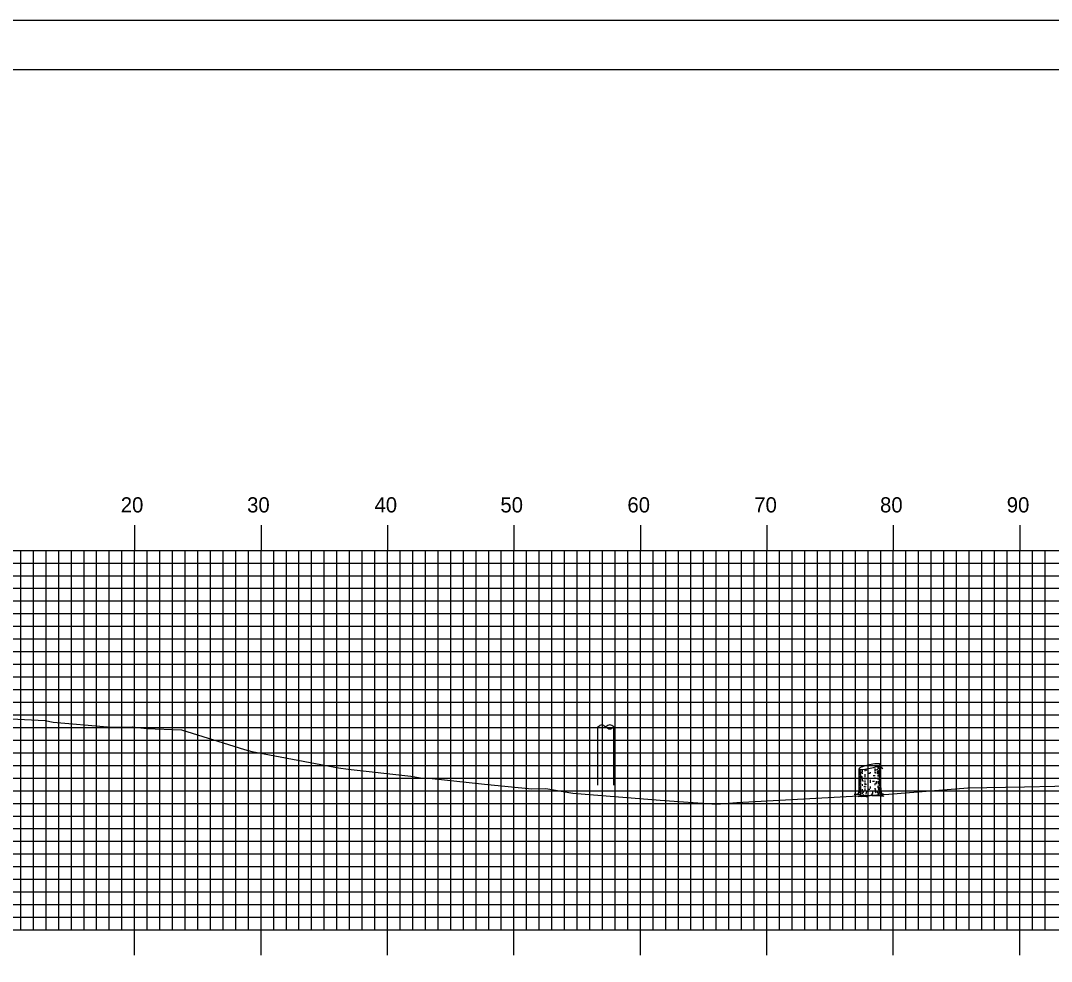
# Model space of a CAD drawing. Extents: x 851300 to 851643, y 366898 to 367118.
# Drawn here: x 851476.5 to 851558, y 367044 to 367118.4 of the extents above; entities that cross this region are included whole.
import ezdxf

# ---------------------------------------------------------------- set-up
doc = ezdxf.new("R2010")
doc.units = 0
for name, color, linetype in [('BORDER', 7, 'Continuous'), ('H_V ANNOTATION', 7, 'Continuous'), ('M_Trees_Conifer_Pay', 7, 'Continuous'), ('MAJOR', 7, 'Continuous'), ('MINOR', 7, 'Continuous'), ('PLOT BOUNDARY', 7, 'Continuous'), ('S_Roadway_Centerline', 7, 'Continuous'), ('S_Utilities_Pole_Power', 7, 'Continuous')]:
    doc.layers.add(name, color=color, linetype=linetype)

msp = doc.modelspace()

# ---------------------------------------------------------------- linework, layer by layer
at = {"layer": 'BORDER'}
msp.add_lwpolyline([(851315.905, 366904.473), (851635.905, 366904.473), (851635.905, 367114.473), (851315.905, 367114.473)], close=True, dxfattribs=at)
at = {"layer": 'M_Trees_Conifer_Pay'}
for p, q in [((851544.469, 367057.903), (851544.469, 367059.55)), ((851542.805, 367057.493), (851542.805, 367059.215)), ((851542.852, 367059.178), (851542.852, 367058.706)), ((851542.911, 367059.166), (851542.911, 367059.069)), ((851542.911, 367058.994), (851542.911, 367058.79)), ((851543.036, 367059.159), (851543.036, 367058.926)), ((851543.036, 367058.886), (851543.036, 367058.811)), ((851543.256, 367059.179), (851543.256, 367059.011)), ((851543.256, 367058.774), (851543.256, 367058.537)), ((851543.661, 367058.947), (851543.661, 367058.852)), ((851544.052, 367059.221), (851544.052, 367059.021)), ((851544.052, 367058.964), (851544.052, 367058.875)), ((851544.28, 367059.417), (851544.28, 367059.194)), ((851544.28, 367059.105), (851544.28, 367059.058)), ((851544.337, 367058.922), (851544.286, 367058.863)), ((851544.398, 367059.478), (851544.398, 367059.315)), ((851544.398, 367059.248), (851544.398, 367059.12)), ((851544.398, 367058.933), (851544.398, 367058.597)), ((851542.852, 367058.642), (851542.852, 367058.334)), ((851542.852, 367058.286), (851542.852, 367057.794)), ((851542.911, 367058.733), (851542.911, 367058.533)), ((851542.911, 367058.486), (851542.911, 367058.15)), ((851542.911, 367058.097), (851542.911, 367057.961)), ((851543.036, 367058.408), (851543.036, 367058.269)), ((851543.036, 367057.998), (851543.036, 367057.856)), ((851543.256, 367058.292), (851543.256, 367058.14)), ((851543.256, 367058.097), (851543.256, 367057.924)), ((851543.661, 367058.334), (851543.661, 367058.26)), ((851543.661, 367058.235), (851543.661, 367058.086)), ((851544.052, 367058.527), (851544.052, 367058.422)), ((851544.052, 367058.056), (851544.052, 367057.909)), ((851544.28, 367058.723), (851544.28, 367058.591)), ((851544.28, 367058.48), (851544.28, 367058.37)), ((851544.28, 367058.235), (851544.28, 367058.093)), ((851544.398, 367058.56), (851544.398, 367058.397)), ((851544.398, 367058.35), (851544.398, 367058.134)), ((851544.398, 367058.103), (851544.398, 367058.029)), ((851544.398, 367057.988), (851544.398, 367057.815)), ((851542.852, 367057.741), (851542.852, 367057.493)), ((851542.911, 367057.862), (851542.911, 367057.483)), ((851543.036, 367057.594), (851543.036, 367057.5)), ((851543.036, 367057.1), (851543.199, 367057.164)), ((851543.256, 367057.646), (851543.256, 367057.493)), ((851543.661, 367057.794), (851543.661, 367057.641)), ((851544.052, 367057.677), (851544.052, 367057.588)), ((851544.28, 367057.866), (851544.28, 367057.693)), ((851543.473, 367057.036), (851543.347, 367057.1))]:
    msp.add_line(p, q, dxfattribs=at)
for points in [[(851544.253, 367059.011), (851544.222, 367058.926), (851544.218, 367058.859), (851544.249, 367058.795)], [(851544.286, 367059.048), (851544.323, 367058.974), (851544.37, 367059.031), (851544.428, 367059.099), (851544.52, 367059.293), (851544.585, 367059.34), (851544.616, 367059.347)], [(851544.301, 367058.795), (851544.337, 367058.922), (851544.401, 367059.038), (851544.432, 367059.105), (851544.501, 367059.252)], [(851544.515, 367059.281), (851544.591, 367059.289), (851544.663, 367059.19)], [(851542.984, 367058.521), (851542.978, 367058.616), (851543.022, 367058.593), (851543.022, 367058.498)], [(851544.123, 367058.122), (851544.136, 367058.045), (851544.183, 367058.056), (851544.171, 367058.222)], [(851544.469, 367057.903), (851544.52, 367057.641), (851544.537, 367057.368), (851544.595, 367057.243), (851544.73, 367057.212), (851544.5, 367057.174), (851544.5, 367057.174), (851544.506, 367057.127), (851544.753, 367057.033), (851544.479, 367057.049), (851544.123, 367057.069), (851543.802, 367057.059), (851543.808, 367057.141), (851543.66, 367057.059), (851543.473, 367057.036), (851543.497, 367056.968), (851543.23, 367057.012), (851543.009, 367056.985), (851542.717, 367057.002), (851543.005, 367057.059), (851543.036, 367057.1), (851542.873, 367057.158), (851542.637, 367057.168), (851542.396, 367057.168), (851542.738, 367057.226), (851542.779, 367057.306), (851542.805, 367057.493)], [(851542.853, 367057.446), (851542.832, 367057.368), (851542.812, 367057.273)], [(851542.931, 367057.426), (851542.937, 367057.31), (851542.884, 367057.222), (851542.873, 367057.158)], [(851543.094, 367057.452), (851543.094, 367057.321), (851543.005, 367057.222)], [(851543.32, 367057.212), (851543.388, 367057.306), (851543.415, 367057.446)], [(851543.808, 367057.141), (851543.883, 367057.283), (851543.892, 367057.384)], [(851544.059, 367057.51), (851544.07, 367057.384), (851544.144, 367057.341)], [(851544.337, 367057.121), (851544.323, 367057.259), (851544.249, 367057.388)], [(851544.296, 367057.615), (851544.37, 367057.51), (851544.375, 367057.337), (851544.5, 367057.174)], [(851544.395, 367057.761), (851544.401, 367057.615), (851544.448, 367057.547), (851544.459, 367057.348)]]:
    msp.add_lwpolyline(points, dxfattribs=at)
for centre, radius, start, end in [((851544.661, 367054.447), 5.179, 95.37941, 101.7194), ((851544.251, 367058.805), 0.802, 79.2194, 95.37941), ((851544.354, 367059.347), 0.251, 71.05013, 79.2194), ((851544.409, 367059.506), 0.0817, 56.7194, 71.05013), ((851544.425, 367059.531), 0.0527, 46.92298, 56.7194), ((851544.439, 367059.546), 0.0314, 34.2194, 46.92298), ((851544.443, 367059.549), 0.0264, 23.40735, 34.2194), ((851544.447, 367059.55), 0.0226, 11.7194, 23.40735), ((851544.447, 367059.55), 0.0226, 0.03145, 11.7194), ((851544.443, 367059.55), 0.0264, 349.2194, 0.03145), ((851542.837, 367059.037), 0.0334, 163.94846, 180), ((851542.837, 367059.037), 0.0334, 180, 196.05154), ((851542.832, 367059.215), 0.0264, 169.2194, 180.03145), ((851542.828, 367059.215), 0.0226, 180.03145, 191.7194), ((851542.848, 367059.04), 0.0441, 196.05154, 210), ((851542.837, 367059.214), 0.0314, 156.51582, 169.2194), ((851542.828, 367059.215), 0.0226, 191.7194, 203.40735), ((851542.831, 367059.216), 0.0264, 203.40735, 214.2194), ((851542.856, 367059.205), 0.0527, 146.7194, 156.51582), ((851542.864, 367059.049), 0.0624, 210, 228.74941), ((851542.836, 367059.219), 0.0314, 214.2194, 226.92298), ((851542.88, 367059.189), 0.0817, 132.38868, 146.7194), ((851542.85, 367059.235), 0.0527, 226.92298, 236.7194), ((851542.866, 367059.259), 0.0817, 236.7194, 251.05013), ((851542.936, 367059.131), 0.172, 228.74941, 240), ((851542.994, 367059.065), 0.251, 124.2194, 132.38868), ((851542.921, 367059.418), 0.251, 251.05013, 259.2194), ((851543.135, 367059.476), 0.571, 240, 240.33672), ((851543.136, 367059.265), 0.571, 240, 247.05866), ((851543.304, 367058.609), 0.802, 108.05939, 124.2194), ((851543.024, 367059.96), 0.802, 259.2194, 275.37941), ((851543.135, 367059.476), 0.571, 246.85973, 257.98457), ((851544.661, 367054.447), 5.179, 101.7194, 108.05939), ((851542.614, 367064.318), 5.179, 275.37941, 281.7194), ((851543.637, 367063.227), 4.124, 264.6955, 266.73309), ((851543.636, 367062.994), 4.124, 268.07512, 270), ((851543.636, 367062.994), 4.124, 270, 270.35814), ((851542.614, 367064.318), 5.179, 281.7194, 288.05939), ((851543.636, 367062.994), 4.124, 275.78493, 277.05584), ((851543.637, 367063.227), 4.124, 276.23804, 278.1032), ((851543.97, 367060.156), 0.802, 288.05939, 304.2194), ((851544.138, 367059.709), 0.571, 278.1032, 284.36665), ((851544.138, 367059.864), 0.571, 284.43166, 292.41325), ((851544.138, 367059.265), 0.571, 284.44928, 297.04285), ((851544.138, 367059.709), 0.571, 297.0237, 300), ((851544.28, 367059.701), 0.251, 304.2194, 312.38868), ((851544.338, 367059.519), 0.172, 300, 311.25059), ((851544.338, 367059.364), 0.172, 300, 311.25059), ((851544.394, 367059.576), 0.0817, 312.38868, 326.7194), ((851544.41, 367059.436), 0.0624, 311.25059, 330), ((851544.41, 367059.282), 0.0624, 311.25059, 330), ((851544.418, 367059.56), 0.0527, 326.7194, 336.51582), ((851544.426, 367059.427), 0.0441, 330, 343.94846), ((851544.426, 367059.273), 0.0441, 330, 343.94846), ((851544.438, 367059.551), 0.0314, 336.51582, 349.2194), ((851544.436, 367059.424), 0.0334, 343.94846, 354.21506), ((851544.436, 367059.27), 0.0334, 343.94846, 354.21506), ((851544.436, 367058.826), 0.0334, 343.94846, 354.21506), ((851542.837, 367058.59), 0.0334, 163.94846, 180), ((851542.837, 367058.59), 0.0334, 180, 196.05154), ((851542.837, 367058.38), 0.0334, 163.94846, 180), ((851542.837, 367058.38), 0.0334, 180, 196.05154), ((851542.837, 367058.143), 0.0334, 163.94846, 180), ((851542.837, 367058.143), 0.0334, 180, 196.05154), ((851542.837, 367057.945), 0.0334, 163.94846, 180), ((851542.848, 367058.593), 0.0441, 196.05154, 210), ((851542.848, 367058.383), 0.0441, 196.05154, 210), ((851542.848, 367058.146), 0.0441, 196.05154, 210), ((851542.864, 367058.602), 0.0624, 210, 228.74941), ((851542.864, 367058.392), 0.0624, 210, 228.74941), ((851542.864, 367058.155), 0.0624, 210, 228.74941), ((851542.936, 367058.685), 0.172, 228.74941, 240), ((851542.936, 367058.475), 0.172, 228.74941, 240), ((851542.936, 367058.238), 0.172, 228.74941, 240), ((851543.135, 367059.03), 0.571, 240, 240.33672), ((851543.135, 367058.82), 0.571, 240, 246.85973), ((851543.135, 367058.583), 0.571, 240, 246.85973), ((851543.135, 367058.82), 0.571, 259.27072, 261.8968), ((851543.636, 367062.337), 4.124, 261.8968, 263.14738), ((851543.636, 367062.547), 4.124, 264.08098, 266.66759), ((851543.636, 367062.1), 4.124, 264.71603, 266.31934), ((851543.636, 367062.337), 4.124, 270, 270.35814), ((851543.636, 367062.337), 4.124, 273.14934, 275.45691), ((851543.637, 367062.783), 4.124, 273.70524, 275.95043), ((851543.636, 367062.547), 4.124, 277.61247, 278.1032), ((851544.137, 367059.03), 0.571, 278.1032, 286.92962), ((851544.137, 367058.583), 0.571, 285.39827, 297.18959), ((851544.137, 367059.03), 0.571, 297.18959, 300), ((851544.137, 367058.82), 0.571, 297.18959, 300), ((851544.336, 367058.685), 0.172, 300, 311.25059), ((851544.336, 367058.475), 0.172, 300, 311.25059), ((851544.408, 367058.602), 0.0624, 311.25059, 330), ((851544.408, 367058.392), 0.0624, 311.25059, 330), ((851544.408, 367057.958), 0.0624, 311.25059, 330), ((851544.424, 367058.593), 0.0441, 330, 343.94846), ((851544.424, 367058.383), 0.0441, 330, 343.94846), ((851544.424, 367057.948), 0.0441, 330, 343.94846), ((851544.435, 367058.59), 0.0334, 343.94846, 354.21506), ((851544.435, 367058.38), 0.0334, 343.94846, 354.21506), ((851544.435, 367057.945), 0.0334, 343.94846, 354.21506), ((851542.837, 367057.75), 0.0334, 163.94846, 180), ((851542.837, 367057.75), 0.0334, 180, 196.05154), ((851542.837, 367057.53), 0.0334, 163.94846, 180), ((851542.837, 367057.53), 0.0334, 180, 196.05154), ((851542.848, 367057.753), 0.0441, 196.05154, 210), ((851542.848, 367057.533), 0.0441, 196.05154, 210), ((851542.864, 367057.762), 0.0624, 210, 228.74941), ((851542.864, 367057.542), 0.0624, 210, 228.74941), ((851542.936, 367057.845), 0.172, 228.74941, 240), ((851542.936, 367057.624), 0.172, 228.74941, 240), ((851543.124, 367058.391), 0.571, 241.23686, 248.02677), ((851543.135, 367058.19), 0.571, 240, 246.85973), ((851543.135, 367057.969), 0.571, 240, 244.53138), ((851543.636, 367061.487), 4.124, 262.44379, 263.51202), ((851543.636, 367061.903), 4.124, 263.49906, 265.83975), ((851543.636, 367061.707), 4.124, 267.81166, 270), ((851543.636, 367061.707), 4.124, 270, 270.13279), ((851543.636, 367061.707), 4.124, 275.78493, 276.78961), ((851543.636, 367061.487), 4.124, 277.36842, 278.1032), ((851544.137, 367057.969), 0.571, 278.1032, 281.63703), ((851544.137, 367058.19), 0.571, 288.50673, 297.27208), ((851544.137, 367058.385), 0.571, 289.29072, 300), ((851544.336, 367058.04), 0.172, 300, 311.25059), ((851544.336, 367057.624), 0.172, 300, 311.25059), ((851544.408, 367057.542), 0.0624, 311.25059, 330), ((851544.424, 367057.533), 0.0441, 330, 343.94846), ((851544.435, 367057.53), 0.0334, 343.94846, 354.21506)]:
    msp.add_arc(centre, radius, start, end, dxfattribs=at)
at = {"layer": 'MAJOR'}
for p, q in [((851485.505, 367078.477), (851485.505, 367076.473)), ((851495.505, 367078.477), (851495.505, 367076.473)), ((851505.505, 367078.477), (851505.505, 367076.473)), ((851515.505, 367078.477), (851515.505, 367076.473)), ((851525.505, 367078.477), (851525.505, 367076.473)), ((851535.505, 367078.477), (851535.505, 367076.473)), ((851545.505, 367078.477), (851545.505, 367076.473)), ((851555.505, 367078.477), (851555.505, 367076.473)), ((851325.505, 367076.473), (851605.505, 367076.473)), ((851325.505, 367076.473), (851605.505, 367076.473)), ((851485.505, 367046.473), (851485.505, 367076.473)), ((851495.505, 367046.473), (851495.505, 367076.473)), ((851505.505, 367046.473), (851505.505, 367076.473)), ((851515.505, 367046.473), (851515.505, 367076.473)), ((851525.505, 367046.473), (851525.505, 367076.473)), ((851535.505, 367046.473), (851535.505, 367076.473)), ((851545.505, 367046.473), (851545.505, 367076.473)), ((851555.505, 367046.473), (851555.505, 367076.473)), ((851325.505, 367071.473), (851605.505, 367071.473)), ((851325.505, 367066.473), (851605.505, 367066.473)), ((851325.505, 367061.473), (851605.505, 367061.473)), ((851325.505, 367056.473), (851605.505, 367056.473)), ((851325.505, 367051.473), (851605.505, 367051.473)), ((851325.505, 367046.473), (851605.505, 367046.473)), ((851325.505, 367046.473), (851605.505, 367046.473)), ((851485.505, 367044.469), (851485.505, 367046.473)), ((851495.505, 367044.469), (851495.505, 367046.473)), ((851505.505, 367044.469), (851505.505, 367046.473)), ((851515.505, 367044.469), (851515.505, 367046.473)), ((851525.505, 367044.469), (851525.505, 367046.473)), ((851535.505, 367044.469), (851535.505, 367046.473)), ((851545.505, 367044.469), (851545.505, 367046.473)), ((851555.505, 367044.469), (851555.505, 367046.473))]:
    msp.add_line(p, q, dxfattribs=at)
at = {"layer": 'MINOR'}
for p, q in [((851476.505, 367046.473), (851476.505, 367076.473)), ((851477.505, 367046.473), (851477.505, 367076.473)), ((851478.505, 367046.473), (851478.505, 367076.473)), ((851479.505, 367046.473), (851479.505, 367076.473)), ((851480.505, 367046.473), (851480.505, 367076.473)), ((851481.505, 367046.473), (851481.505, 367076.473)), ((851482.505, 367046.473), (851482.505, 367076.473)), ((851483.505, 367046.473), (851483.505, 367076.473)), ((851484.505, 367046.473), (851484.505, 367076.473)), ((851486.505, 367046.473), (851486.505, 367076.473)), ((851487.505, 367046.473), (851487.505, 367076.473)), ((851488.505, 367046.473), (851488.505, 367076.473)), ((851489.505, 367046.473), (851489.505, 367076.473)), ((851490.505, 367046.473), (851490.505, 367076.473)), ((851491.505, 367046.473), (851491.505, 367076.473)), ((851492.505, 367046.473), (851492.505, 367076.473)), ((851493.505, 367046.473), (851493.505, 367076.473)), ((851494.505, 367046.473), (851494.505, 367076.473)), ((851496.505, 367046.473), (851496.505, 367076.473)), ((851497.505, 367046.473), (851497.505, 367076.473)), ((851498.505, 367046.473), (851498.505, 367076.473)), ((851499.505, 367046.473), (851499.505, 367076.473)), ((851500.505, 367046.473), (851500.505, 367076.473)), ((851501.505, 367046.473), (851501.505, 367076.473)), ((851502.505, 367046.473), (851502.505, 367076.473)), ((851503.505, 367046.473), (851503.505, 367076.473)), ((851504.505, 367046.473), (851504.505, 367076.473)), ((851506.505, 367046.473), (851506.505, 367076.473)), ((851507.505, 367046.473), (851507.505, 367076.473)), ((851508.505, 367046.473), (851508.505, 367076.473)), ((851509.505, 367046.473), (851509.505, 367076.473)), ((851510.505, 367046.473), (851510.505, 367076.473)), ((851511.505, 367046.473), (851511.505, 367076.473)), ((851512.505, 367046.473), (851512.505, 367076.473)), ((851513.505, 367046.473), (851513.505, 367076.473)), ((851514.505, 367046.473), (851514.505, 367076.473)), ((851516.505, 367046.473), (851516.505, 367076.473)), ((851517.505, 367046.473), (851517.505, 367076.473)), ((851518.505, 367046.473), (851518.505, 367076.473)), ((851519.505, 367046.473), (851519.505, 367076.473)), ((851520.505, 367046.473), (851520.505, 367076.473)), ((851521.505, 367046.473), (851521.505, 367076.473)), ((851522.505, 367046.473), (851522.505, 367076.473)), ((851523.505, 367046.473), (851523.505, 367076.473)), ((851524.505, 367046.473), (851524.505, 367076.473)), ((851526.505, 367046.473), (851526.505, 367076.473)), ((851527.505, 367046.473), (851527.505, 367076.473)), ((851528.505, 367046.473), (851528.505, 367076.473)), ((851529.505, 367046.473), (851529.505, 367076.473)), ((851530.505, 367046.473), (851530.505, 367076.473)), ((851531.505, 367046.473), (851531.505, 367076.473)), ((851532.505, 367046.473), (851532.505, 367076.473)), ((851533.505, 367046.473), (851533.505, 367076.473)), ((851534.505, 367046.473), (851534.505, 367076.473)), ((851536.505, 367046.473), (851536.505, 367076.473)), ((851537.505, 367046.473), (851537.505, 367076.473)), ((851538.505, 367046.473), (851538.505, 367076.473)), ((851539.505, 367046.473), (851539.505, 367076.473)), ((851540.505, 367046.473), (851540.505, 367076.473)), ((851541.505, 367046.473), (851541.505, 367076.473)), ((851542.505, 367046.473), (851542.505, 367076.473)), ((851543.505, 367046.473), (851543.505, 367076.473)), ((851544.505, 367046.473), (851544.505, 367076.473)), ((851546.505, 367046.473), (851546.505, 367076.473)), ((851547.505, 367046.473), (851547.505, 367076.473)), ((851548.505, 367046.473), (851548.505, 367076.473)), ((851549.505, 367046.473), (851549.505, 367076.473)), ((851550.505, 367046.473), (851550.505, 367076.473)), ((851551.505, 367046.473), (851551.505, 367076.473)), ((851552.505, 367046.473), (851552.505, 367076.473)), ((851553.505, 367046.473), (851553.505, 367076.473)), ((851554.505, 367046.473), (851554.505, 367076.473)), ((851556.505, 367046.473), (851556.505, 367076.473)), ((851557.505, 367046.473), (851557.505, 367076.473)), ((851325.505, 367075.473), (851605.505, 367075.473)), ((851325.505, 367074.473), (851605.505, 367074.473)), ((851325.505, 367073.473), (851605.505, 367073.473)), ((851325.505, 367072.473), (851605.505, 367072.473)), ((851325.505, 367070.473), (851605.505, 367070.473)), ((851325.505, 367069.473), (851605.505, 367069.473)), ((851325.505, 367068.473), (851605.505, 367068.473)), ((851325.505, 367067.473), (851605.505, 367067.473)), ((851325.505, 367065.473), (851605.505, 367065.473)), ((851325.505, 367064.473), (851605.505, 367064.473)), ((851325.505, 367063.473), (851605.505, 367063.473)), ((851325.505, 367062.473), (851605.505, 367062.473)), ((851325.505, 367060.473), (851605.505, 367060.473)), ((851325.505, 367059.473), (851605.505, 367059.473)), ((851325.505, 367058.473), (851605.505, 367058.473)), ((851325.505, 367057.473), (851605.505, 367057.473)), ((851325.505, 367055.473), (851605.505, 367055.473)), ((851325.505, 367054.473), (851605.505, 367054.473)), ((851325.505, 367053.473), (851605.505, 367053.473)), ((851325.505, 367052.473), (851605.505, 367052.473)), ((851325.505, 367050.473), (851605.505, 367050.473)), ((851325.505, 367049.473), (851605.505, 367049.473)), ((851325.505, 367048.473), (851605.505, 367048.473)), ((851325.505, 367047.473), (851605.505, 367047.473))]:
    msp.add_line(p, q, dxfattribs=at)
at = {"layer": 'PLOT BOUNDARY'}
msp.add_lwpolyline([(851299.718, 366898.355), (851639.718, 366898.355), (851639.718, 367118.355), (851299.718, 367118.355)], close=True, dxfattribs=at)
at = {"layer": 'S_Roadway_Centerline'}
msp.add_lwpolyline([(851471.345, 367063.358), (851478.43, 367063.023), (851479.06, 367062.903), (851483.356, 367062.53), (851485.277, 367062.49), (851485.335, 367062.526), (851486.44, 367062.401), (851489.209, 367062.28), (851494.202, 367060.739), (851494.774, 367060.58), (851501.628, 367059.276), (851502.39, 367059.169), (851507.356, 367058.621), (851508.285, 367058.463), (851509.027, 367058.445), (851513.177, 367058), (851516.911, 367057.62), (851518.02, 367057.643), (851520.166, 367057.289), (851527.078, 367056.738), (851531.511, 367056.416), (851533.129, 367056.548), (851545.163, 367057.195), (851551.404, 367057.689), (851555.873, 367057.785), (851563.084, 367057.93)], dxfattribs=at)
at = {"layer": 'S_Utilities_Pole_Power'}
for p, q in [((851522.144, 367057.898), (851522.141, 367062.518)), ((851522.144, 367062.518), (851522.301, 367062.628)), ((851522.613, 367062.628), (851522.769, 367062.518)), ((851522.926, 367062.628), (851522.769, 367062.518)), ((851522.769, 367062.518), (851522.926, 367062.407)), ((851523.394, 367062.518), (851523.238, 367062.628)), ((851523.238, 367062.407), (851523.394, 367062.518)), ((851523.394, 367057.898), (851523.391, 367062.518))]:
    msp.add_line(p, q, dxfattribs=at)
for centre, start, end in [((851522.457, 367062.407), 90, 125.26439), ((851522.457, 367062.407), 54.73561, 90), ((851523.082, 367062.407), 90, 125.26439), ((851523.082, 367062.628), 234.73561, 270), ((851523.082, 367062.407), 54.73561, 90), ((851523.082, 367062.628), 270, 305.26439)]:
    msp.add_arc(centre, 0.271, start, end, dxfattribs=at)

# ---------------------------------------------------------------- texts
at = {"layer": 'H_V ANNOTATION'}
for s, p in [('20', (851484.413, 367079.473)), ('30', (851494.402, 367079.473)), ('40', (851504.477, 367079.473)), ('50', (851514.434, 367079.473)), ('60', (851524.477, 367079.473)), ('70', (851534.509, 367079.473)), ('80', (851544.456, 367079.473)), ('90', (851554.477, 367079.473))]:
    msp.add_text(s, height=1.2, dxfattribs=at).set_placement(p)

doc.saveas('drawing.dxf')
